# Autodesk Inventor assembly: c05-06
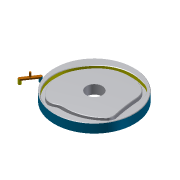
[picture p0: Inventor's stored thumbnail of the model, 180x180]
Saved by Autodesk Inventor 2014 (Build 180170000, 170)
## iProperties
Created: 2010-11
Part Number: c05-06
Document SubType Name: Assembly
Designer: Thom Tremblay
Author: Thom Tremblay
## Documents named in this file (3)
- C:\Inventor 2014 Essentials\Assemblies\Chapter 05\c05-06.iam
- C:\Inventor 2014 Essentials\Parts\Chapter 05\c05-05.ipt
- C:\Inventor 2014 Essentials\Parts\Chapter 05\c05-06.ipt
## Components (2 placed, 2 different names)
1. c05-05:1 — Mate:1, Tangent:1
2. c05-06:1 — Mate:1, Tangent:1
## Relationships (2: Mate 1, Tangent 1)
- Mate:1: c05-05:1 ↔ c05-06:1
- Tangent:1: c05-05:1 ↔ c05-06:1
